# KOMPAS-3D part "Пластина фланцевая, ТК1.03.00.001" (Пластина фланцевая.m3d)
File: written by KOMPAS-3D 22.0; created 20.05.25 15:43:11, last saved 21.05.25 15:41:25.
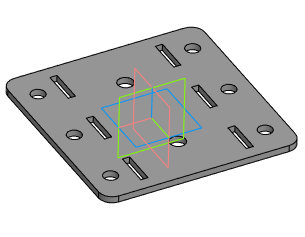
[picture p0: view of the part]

Document properties: Автор: TC; Полное имя файла: ТК1.03.00.001 - Пластина фланцевая.cdw

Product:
- Part/product: Пластина фланцевая  | designation ТК1.03.00.001
    Масса: 0.815547
    Форматы листов документа: A4

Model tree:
1. Эскиз:1
2. Элемент выдавливания:1
     Расстояние 1 = 5
3. Скругление:1  (with: Элемент выдавливания:1)
     Радиус = 10
4. Эскиз:2  (with: Элемент выдавливания:1)
5. Элемент выдавливания:2
     Расстояние 2 = 5
6. Зеркальный массив:1
7. Экземпляр ( 1 )
8. Экземпляр ( 2 )  (with: Элемент выдавливания:2)
9. Эскиз:3  (with: Элемент выдавливания:1, Элемент выдавливания:2)
10. Элемент выдавливания:3
     Расстояние 2 = 10

Expressions: M/2
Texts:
  ТК1.03.00.001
